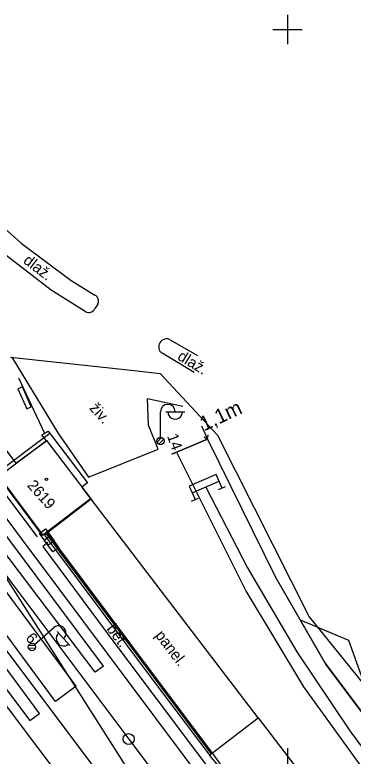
# Model space of a CAD drawing. Extents: x -804166 to -803706, y -1151030 to -1150147.
# Drawn here: x -804037.2 to -803991, y -1150299.1 to -1150198 of the extents above; entities that cross this region are included whole.
import ezdxf

# ---------------------------------------------------------------- set-up
doc = ezdxf.new("R2010")
doc.units = 0
for name, color, linetype in [('0381KM032-037P - Vrstva 1', 7, 'Continuous'), ('0381KM032-037P - Vrstva 13', 7, 'Continuous'), ('0381KM032-037P - Vrstva 14', 7, 'Continuous'), ('0381KM032-037P - Vrstva 15', 7, 'Continuous'), ('0381KM032-037P - Vrstva 16', 7, 'Continuous'), ('0381KM032-037P - Vrstva 17', 7, 'Continuous'), ('0381KM032-037P - Vrstva 23', 7, 'Continuous'), ('0381KM032-037P - Vrstva 25', 7, 'Continuous'), ('0381KM032-037P - Vrstva 33', 7, 'Continuous'), ('0381KM032-037P - Vrstva 4', 7, 'Continuous'), ('0381KM032-037P - Vrstva 49', 7, 'Continuous'), ('0381KM032-037P - Vrstva 51', 7, 'Continuous'), ('0381KM032-037P - Vrstva 55', 7, 'Continuous'), ('0381KM032-037P - Vrstva 57', 7, 'Continuous'), ('0381KM032-037P - Vrstva 59', 7, 'Continuous'), ('0381KM032-037P - Vrstva 7', 7, 'Continuous'), ('hran DP - hran DP', 7, 'Continuous'), ('krizky_1000 - Vrstva 1', 7, 'Continuous'), ('vyt_sit - polygon', 7, 'Continuous')]:
    doc.layers.add(name, color=color, linetype=linetype)

msp = doc.modelspace()

# ---------------------------------------------------------------- linework, layer by layer
at = {"layer": '0381KM032-037P - Vrstva 1'}
for points in [[(-804087.93, -1150205.28), (-804078.71, -1150215.28), (-804072.37, -1150222.52), (-804072.08, -1150222.85), (-804071.47, -1150223.58), (-804065.48, -1150230.82), (-804059.47, -1150238.51), (-804055.55, -1150243.68), (-804054.36, -1150245.27), (-804043.89, -1150259.22), (-804035.37, -1150270.61), (-804034.4, -1150271.93), (-804017.97, -1150293.92), (-804002.6, -1150314.46), (-803985.38, -1150337.43), (-803955.87, -1150376.72)], [(-804089.35, -1150206.44), (-804078.67, -1150220.7), (-804069.15, -1150233.38), (-804067.86, -1150235.11), (-804059.28, -1150246.53), (-804058.07, -1150248.16), (-804048.7, -1150260.65), (-804037.85, -1150275.13), (-804021.63, -1150296.76), (-804006.14, -1150317.34), (-803988.98, -1150340.29), (-803981.9, -1150349.73)], [(-804090.39, -1150214.38), (-804086.65, -1150219.55), (-804073.82, -1150237.11), (-804072.56, -1150238.83), (-804064.05, -1150250.31), (-804062.81, -1150251.97), (-804052.29, -1150266.05), (-804042.5, -1150279.11), (-804026.55, -1150300.33), (-804011.27, -1150320.63), (-803993.37, -1150344.49), (-803965.17, -1150382.07), (-803953.84, -1150397.19)], [(-804093.97, -1150217.42), (-804088.17, -1150225.67), (-804077.51, -1150240.28), (-804068.52, -1150252.21), (-804067.31, -1150253.81), (-804055.01, -1150270.12), (-804046.09, -1150281.93), (-804030.05, -1150303.21), (-804014.76, -1150323.52), (-803996.92, -1150347.35), (-803968.88, -1150385.42), (-803942.6, -1150419.03)], [(-804011.14, -1150262.39), (-804005.45, -1150273.41), (-803998.73, -1150284.85), (-803991.51, -1150295.63), (-803978.8, -1150312.77), (-803963.69, -1150332.99), (-803952.21, -1150348.36), (-803946.3, -1150356.39), (-803941.6, -1150363.14), (-803936.71, -1150370.83), (-803932.05, -1150378.84), (-803927.78, -1150386.91), (-803924.06, -1150395.18), (-803920.62, -1150403.65), (-803918.06, -1150410.86), (-803915.07, -1150420.32), (-803912.96, -1150427.25), (-803910.49, -1150435.34), (-803907.33, -1150445.05), (-803903.67, -1150454.38), (-803897.94, -1150464.6), (-803891.97, -1150476.6)]]:
    msp.add_lwpolyline(points, dxfattribs=at)
at = {"layer": '0381KM032-037P - Vrstva 13'}
for p, q in [((-804011.73, -1150254.06), (-804010.87, -1150255.86)), ((-804032.73, -1150268.64), (-804030.94, -1150271.03)), ((-804030.94, -1150271.03), (-804018.44, -1150287.75)), ((-804018.44, -1150287.75), (-804010.19, -1150298.7)), ((-804010.19, -1150298.7), (-804007.43, -1150302.56))]:
    msp.add_line(p, q, dxfattribs=at)
for points in [[(-804011.36, -1150255.54), (-804010.87, -1150255.86), (-804010.82, -1150255.28)], [(-804010.87, -1150255.86), (-804015.74, -1150257.89), (-804015.74, -1150257.89), (-804010.87, -1150255.86)]]:
    msp.add_lwpolyline(points, dxfattribs=at)
at = {"layer": '0381KM032-037P - Vrstva 14'}
for p, q in [((-804028.77, -1150289.52), (-804076.45, -1150225.31)), ((-804031.59, -1150291.62), (-804079.27, -1150227.4)), ((-804033.77, -1150293.24), (-804081.46, -1150229.02)), ((-804083.37, -1150230.42), (-804035.09, -1150294.23)), ((-804025.08, -1150286.79), (-804026.2, -1150287.61)), ((-804028.77, -1150289.52), (-804031.59, -1150291.62)), ((-804035.09, -1150294.23), (-804033.77, -1150293.24))]:
    msp.add_line(p, q, dxfattribs=at)
for points in [[(-804026.2, -1150287.61), (-804040.5, -1150268.78), (-804056.56, -1150247.39), (-804058.99, -1150244.12), (-804066.4, -1150234.12), (-804074.2, -1150223.73)], [(-804025.08, -1150286.79), (-804066.44, -1150231.31), (-804073.38, -1150223.27)]]:
    msp.add_lwpolyline(points, dxfattribs=at)
at = {"layer": '0381KM032-037P - Vrstva 15'}
for p, q in [((-804012.98, -1150263.18), (-804009.3, -1150261.6)), ((-804009.37, -1150262.72), (-804008.45, -1150262.33)), ((-804013.05, -1150264.29), (-804012.13, -1150263.9))]:
    msp.add_line(p, q, dxfattribs=at)
msp.add_lwpolyline([(-804008.91, -1150262.52), (-804009.69, -1150260.68), (-804013.37, -1150262.26), (-804012.59, -1150264.1)], dxfattribs=at)
at = {"layer": '0381KM032-037P - Vrstva 16'}
for p, q in [((-804026.77, -1150264.06), (-804032.89, -1150268.75)), ((-804003.99, -1150293.85), (-804026.77, -1150264.06)), ((-804033.12, -1150268.93), (-804032.89, -1150268.75)), ((-804018.6, -1150287.79), (-804010.38, -1150298.76)), ((-804018.83, -1150288.05), (-804010.58, -1150299)), ((-804010.38, -1150298.76), (-804003.99, -1150293.85)), ((-804010.58, -1150299), (-804010.38, -1150298.76))]:
    msp.add_line(p, q, dxfattribs=at)
for points in [[(-804033.12, -1150268.93), (-804031.33, -1150271.33), (-804018.83, -1150288.05)], [(-804032.89, -1150268.75), (-804031.1, -1150271.13), (-804018.6, -1150287.79)], [(-804032.64, -1150269.93), (-804033.34, -1150270.47), (-804023.51, -1150283.74), (-804006.75, -1150306.05), (-804006.63, -1150306.04)], [(-804003.99, -1150293.85), (-803995.7, -1150304.68), (-804002.75, -1150311.23), (-804006.63, -1150306.04), (-804005.86, -1150304.94), (-804007.53, -1150302.64), (-804010.58, -1150299)]]:
    msp.add_lwpolyline(points, dxfattribs=at)
at = {"layer": '0381KM032-037P - Vrstva 17'}
msp.add_line((-804033.09, -1150255.01), (-804036.6, -1150247.55), dxfattribs=at)
at = {"layer": '0381KM032-037P - Vrstva 23'}
for points in [[(-804034.08, -1150269.19), (-804040.27, -1150260.96), (-804032.39, -1150255.05)], [(-804039.34, -1150260.91), (-804032.82, -1150256.05), (-804026.77, -1150264.06)], [(-804026.77, -1150264.06), (-804033.29, -1150268.94), (-804039.34, -1150260.91)]]:
    msp.add_lwpolyline(points, dxfattribs=at)
at = {"layer": '0381KM032-037P - Vrstva 25'}
for p, q in [((-804017.3, -1150255.61), (-804017.3, -1150252.11)), ((-804016.59, -1150252.11), (-804013.99, -1150252.11)), ((-804017.77, -1150256.26), (-804017.15, -1150255.64)), ((-804017.53, -1150256.55), (-804016.86, -1150255.87)), ((-804034.45, -1150283.87), (-804031.83, -1150281.54)), ((-804031.36, -1150282.07), (-804029.64, -1150284.01)), ((-804035.31, -1150284.31), (-804034.35, -1150284.37)), ((-804035.25, -1150283.94), (-804034.37, -1150283.99))]:
    msp.add_line(p, q, dxfattribs=at)
for points in [[(-804033.78, -1150268.7), (-804032.98, -1150268.1), (-804031.79, -1150269.72), (-804032.6, -1150270.31), (-804033.78, -1150268.7)], [(-804033.14, -1150269.61), (-804032.33, -1150269.03), (-804031.17, -1150270.66), (-804031.98, -1150271.24), (-804033.14, -1150269.61)]]:
    msp.add_lwpolyline(points, dxfattribs=at)
for centre in [(-804017.3, -1150256.11), (-804017.3, -1150256.11), (-804034.82, -1150284.2), (-804034.82, -1150284.2)]:
    msp.add_circle(centre, 0.5, dxfattribs=at)
for centre, start, end in [((-804016.3, -1150252.11), 0, 180), ((-804015.3, -1150252.13), 179.2974, 0.7026), ((-804031.17, -1150282.29), 311.5784, 131.5784), ((-804030.51, -1150283.05), 130.8758, 312.281)]:
    msp.add_arc(centre, 1, start, end, dxfattribs=at)
at = {"layer": '0381KM032-037P - Vrstva 33'}
msp.add_lwpolyline([(-804035.53, -1150251.74), (-804034.92, -1150251.47), (-804036.13, -1150248.73), (-804036.75, -1150249.01)], close=True, dxfattribs=at)
at = {"layer": '0381KM032-037P - Vrstva 4'}
for points in [[(-804015.09, -1150257.7), (-804005.61, -1150276.65), (-803997.81, -1150289.61), (-803985.99, -1150305.97), (-803963.83, -1150335.54), (-803947.69, -1150357.39), (-803941.6, -1150366.02), (-803933.49, -1150379.54), (-803925.57, -1150395.83), (-803919.57, -1150411.36), (-803915.11, -1150425.7)], [(-804033.34, -1150270.47), (-804023.51, -1150283.74), (-804006.75, -1150306.05), (-804002.75, -1150311.23), (-803984.52, -1150335.59), (-803962.04, -1150365.45)]]:
    msp.add_lwpolyline(points, dxfattribs=at)
at = {"layer": '0381KM032-037P - Vrstva 49'}
for points in [[(-804010.87, -1150255.86), (-804001.61, -1150274.67), (-803994.7, -1150286.68), (-803981.46, -1150304.36), (-803936.05, -1150366.09), (-803921.77, -1150392.54), (-803912.22, -1150419.28), (-803908.81, -1150430.91)], [(-804010.87, -1150255.86), (-804010.87, -1150255.86), (-804001.65, -1150274.6), (-803994.86, -1150286.39), (-803989.31, -1150293.81), (-803989.41, -1150293.74)], [(-803998.25, -1150280.5), (-803991.69, -1150283.27), (-803989.47, -1150289.34)]]:
    msp.add_lwpolyline(points, dxfattribs=at)
at = {"layer": '0381KM032-037P - Vrstva 51'}
for p, q in [((-804025.88, -1150237.56), (-804026.25, -1150238.06)), ((-804015.96, -1150242.31), (-804012.26, -1150244.47)), ((-804012.73, -1150246.76), (-804017.09, -1150244.14))]:
    msp.add_line(p, q, dxfattribs=at)
for points in [[(-804044.22, -1150222.03), (-804036.31, -1150229.15), (-804029.46, -1150234.23), (-804026.23, -1150236.21)], [(-804027.57, -1150238.43), (-804032.18, -1150235.55), (-804038.4, -1150230.77), (-804045.96, -1150223.83), (-804046.63, -1150224.5), (-804046.89, -1150224.2)], [(-804037.56, -1150244.69), (-804031.31, -1150254.99), (-804027.1, -1150261.05), (-804017.62, -1150257.21), (-804018.95, -1150253.97), (-804019.08, -1150250.33), (-804014.25, -1150251.35)], [(-804015.09, -1150257.7), (-804005.61, -1150276.65), (-803997.81, -1150289.61), (-803985.99, -1150305.97), (-803963.83, -1150335.54), (-803947.69, -1150357.39), (-803941.6, -1150366.02), (-803933.49, -1150379.54), (-803925.57, -1150395.83), (-803919.57, -1150411.36), (-803915.11, -1150425.7)]]:
    msp.add_lwpolyline(points, dxfattribs=at)
for centre, major_axis, ratio, start_param, end_param in [((-804026.69, -1150237.05), (0.085, 0.955), 0.999815, 4.242277, 5.86844), ((-804027.06, -1150237.72), (-0.618, -0.618), 0.999716, 0.15876, 1.957098), ((-804016.46, -1150243.27), (-0.422, -0.994), 0.999309, 3.06867, 6.055029)]:
    msp.add_ellipse(centre, major_axis=major_axis, ratio=ratio, start_param=start_param, end_param=end_param, dxfattribs=at)
at = {"layer": '0381KM032-037P - Vrstva 55'}
msp.add_lwpolyline([(-804042.49, -1150256.99), (-804040.01, -1150255.2), (-804037.01, -1150259.13), (-804032.83, -1150256.09), (-804033.46, -1150255.26), (-804032.63, -1150254.75), (-804027.25, -1150261.82), (-804028.04, -1150262.42), (-804026.84, -1150264.01), (-804033.36, -1150268.97), (-804039.39, -1150261.01)], close=True, dxfattribs=at)
at = {"layer": '0381KM032-037P - Vrstva 59'}
msp.add_circle((-804032.85, -1150261.34), 0.175, dxfattribs=at)
at = {"layer": '0381KM032-037P - Vrstva 7'}
msp.add_circle((-804021.64, -1150296.75), 0.75, dxfattribs=at)
at = {"layer": 'hran DP - hran DP'}
for p, q in [((-804037.73, -1150244.68), (-804020.87, -1150246.51)), ((-804020.87, -1150246.51), (-804017.32, -1150246.9)), ((-804017.32, -1150246.9), (-804009.55, -1150255.32)), ((-804009.55, -1150255.32), (-803997.02, -1150280.06)), ((-803997.02, -1150280.06), (-803982.8, -1150297.76))]:
    msp.add_line(p, q, dxfattribs=at)
at = {"layer": 'krizky_1000 - Vrstva 1'}
for points in [[(-804000, -1150198), (-804000, -1150202)], [(-804002, -1150200), (-803998, -1150200)], [(-804000, -1150298), (-804000, -1150302)]]:
    msp.add_lwpolyline(points, dxfattribs=at)
at = {"layer": 'vyt_sit - polygon'}
msp.add_line((-804079.95, -1150209.42), (-804016.51, -1150309.12), dxfattribs=at)

# ---------------------------------------------------------------- texts
at = {"layer": '0381KM032-037P - Vrstva 13'}
msp.add_text('1,1m', height=2, rotation=25.39, dxfattribs=at).set_placement((-804011.36, -1150254.81))
at = {"layer": '0381KM032-037P - Vrstva 16'}
for s, rotation, p in [('bet.', 306.5425, (-804024.71, -1150281.72)), ('panel.', 307.3989, (-804018.1, -1150282.62))]:
    msp.add_text(s, height=1.5, rotation=rotation, dxfattribs=at).set_placement(p)
at = {"layer": '0381KM032-037P - Vrstva 25'}
for s, rotation, p in [('14', 290, (-804016.43, -1150255.42)), ('6', 311.5784, (-804035.78, -1150283.05))]:
    msp.add_text(s, height=1.5, rotation=rotation, dxfattribs=at).set_placement(p)
at = {"layer": '0381KM032-037P - Vrstva 51'}
for s, rotation, p in [('dlaž.', 322.4479, (-804036.12, -1150231.74)), ('dlaž.', 328.9976, (-804015.11, -1150244.94)), ('živ.', 312.047, (-804027.08, -1150251.68))]:
    msp.add_text(s, height=1.5, rotation=rotation, dxfattribs=at).set_placement(p)
at = {"layer": '0381KM032-037P - Vrstva 57'}
msp.add_text('2619', height=1.5, rotation=311.6073, dxfattribs=at).set_placement((-804035.56, -1150262.21))

doc.saveas('drawing.dxf')
